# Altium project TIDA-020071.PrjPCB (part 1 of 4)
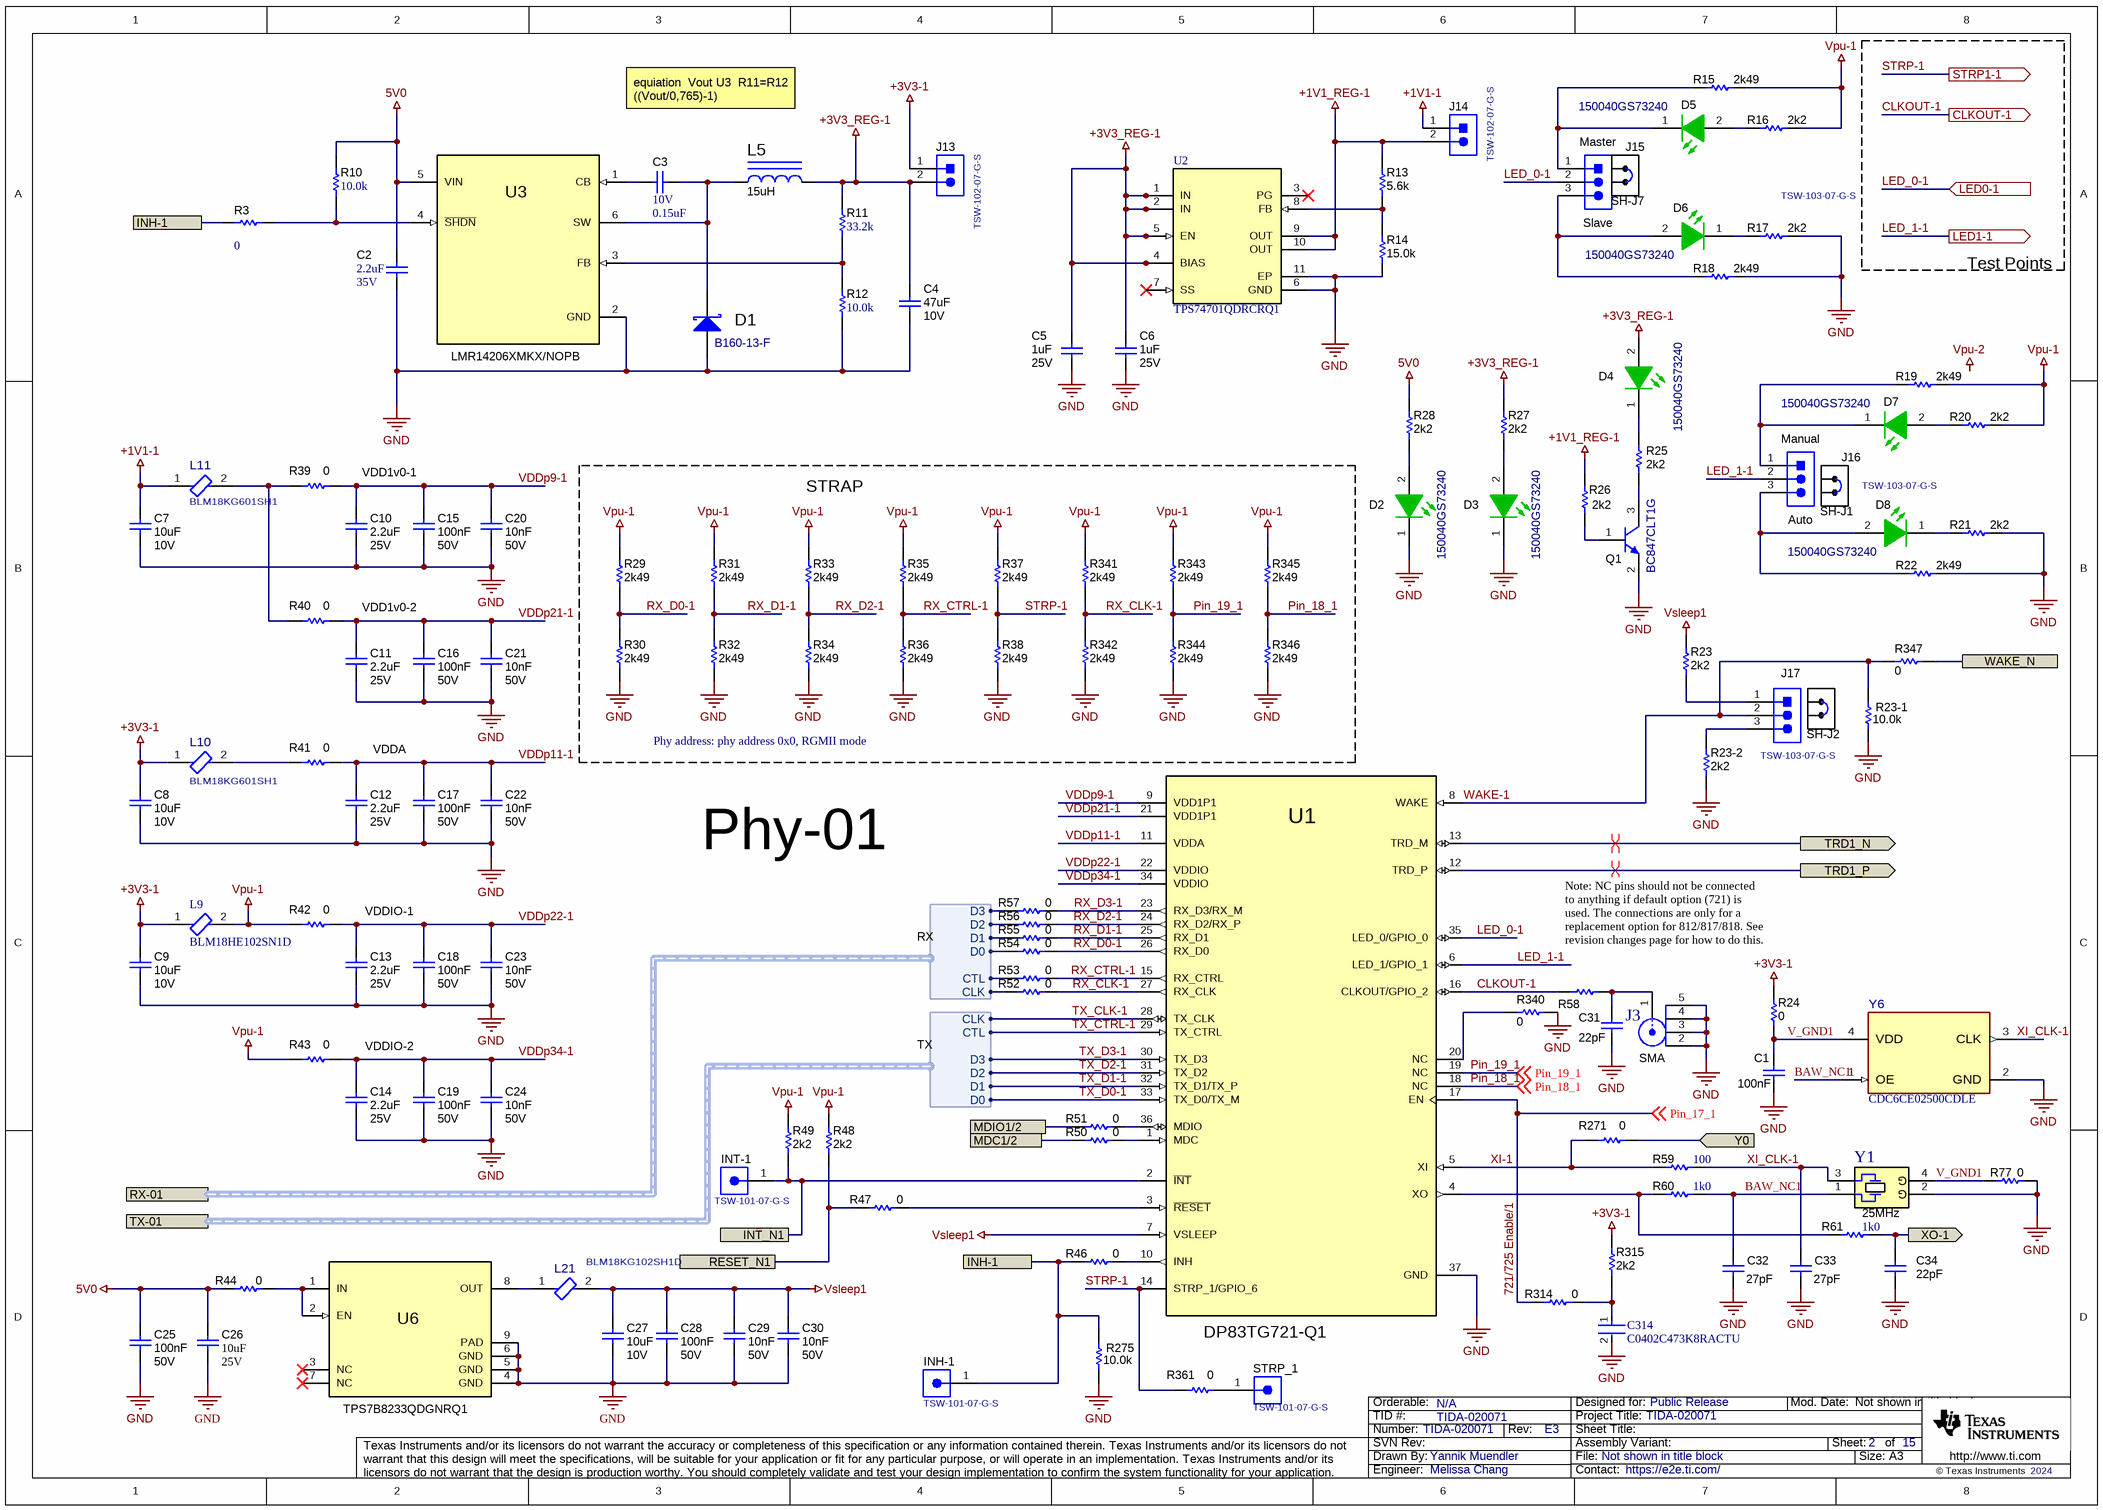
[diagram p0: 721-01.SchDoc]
CopyrightYear: 2024; DrawnBy: Yannik Muendler; EVM_orderable: N/A; PCB_Layout: TESSOLVE; PCB_Rev: E3; PRJ_Customer: Public Release; PRJ_Engineer: Melissa Chang; PRJ_Number: TIDA-020071; PRJ_Title: TIDA-020071; SCH_Rev: E3; TechSupport: https://e2e.ti.com/; TID: TIDA-020071
15 sheets, 793 parts. Net scope: flat (ports and power ports of the same name join across sheets).
Board file: TIDA-020071.PcbDoc
Sheets:
  721-01.SchDoc
  721-02.SchDoc
  818-03.SchDoc
  818-04.SchDoc
  CLOCK.SchDoc
  AVB Headers.SchDoc
  Connector.SchDoc
  Conn-Rb-01.SchDoc
  Conn-Rb-02.SchDoc
  Conn-TE-01.SchDoc
  Conn-TE-02.SchDoc
  Hardware.SchDoc
  MDIO_MUX.SchDoc
  HSS and Memory.SchDoc
  Reset.SchDoc

## Sheet 721-01.SchDoc
size A3; Date: Not shown in title block; ApprovedBy: Not shown in title block; CheckedBy: Not shown in title block; Author: Not shown in title block; CompanyName: Not shown in title block; Engineer: Not shown in title block; Organization: Not shown in title block; Address1: Not shown in title block; Address2: Not shown in title block; Address3: Not shown in title block; Address4: Not shown in title block; DocumentNumber: 2; Revision: Use project parameter SCH_Rev; SheetNumber: 2; SheetTotal: 15; PageSetup: Record=PageOptions¦CenterHorizontal=True¦CenterVertical=True¦PrintScale=1.00¦XCorrection=1.00¦YCorrection=1.00¦PrintKind=0¦BorderSize=5000000¦LeftOffset=0¦BottomOffset=0¦Orientation=2¦PaperLength=1000¦PaperWidth=1000¦Scale=100¦PaperSource=15¦PrintQuality=600¦MediaType=1¦DitherType=10¦PaperKind=Letter¦PrintScaleMode=1

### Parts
C1  ValueDisplayed: 100nF  [0402]  (hidden comment: C1005X5R1H104K050BB)
C2  VDC_V: 35V  ValueDisplayed: 2.2uF  [0603]  (hidden comment: C1608X5R1V225K080AC)
C3  VDC_V: 10V  ValueDisplayed: 0.15uF  [0402]  (hidden comment: GRM155R61A154KE19D)
C4  VDC_V: 10V  ValueDisplayed: 47uF  [0805_HV]  (hidden comment: C2012X5R1A476M125AC)
C5  VDC_V: 25V  ValueDisplayed: 1uF  [0402]  (hidden comment: GRM155R61E105KA12D)
C6  VDC_V: 25V  ValueDisplayed: 1uF  [0402]  (hidden comment: GRM155R61E105KA12D)
C7  VDC_V: 10V  ValueDisplayed: 10uF  [0402]  (hidden comment: GRM155R61A106ME11)
C8  VDC_V: 10V  ValueDisplayed: 10uF  [0402]  (hidden comment: GRM155R61A106ME11)
C9  VDC_V: 10V  ValueDisplayed: 10uF  [0402]  (hidden comment: GRM155R61A106ME11)
C10  VDC_V: 25V  ValueDisplayed: 2.2uF  [0402]  (hidden comment: C1005X5R1E225K050BC)
C11  VDC_V: 25V  ValueDisplayed: 2.2uF  [0402]  (hidden comment: C1005X5R1E225K050BC)
C12  VDC_V: 25V  ValueDisplayed: 2.2uF  [0402]  (hidden comment: C1005X5R1E225K050BC)
C13  VDC_V: 25V  ValueDisplayed: 2.2uF  [0402]  (hidden comment: C1005X5R1E225K050BC)
C14  VDC_V: 25V  ValueDisplayed: 2.2uF  [0402]  (hidden comment: C1005X5R1E225K050BC)
C15  VDC_V: 50V  ValueDisplayed: 100nF  [0402]  (hidden comment: C1005X5R1H104K050BB)
C16  VDC_V: 50V  ValueDisplayed: 100nF  [0402]  (hidden comment: C1005X5R1H104K050BB)
C17  VDC_V: 50V  ValueDisplayed: 100nF  [0402]  (hidden comment: C1005X5R1H104K050BB)
C18  VDC_V: 50V  ValueDisplayed: 100nF  [0402]  (hidden comment: C1005X5R1H104K050BB)
C19  VDC_V: 50V  ValueDisplayed: 100nF  [0402]  (hidden comment: C1005X5R1H104K050BB)
C20  VDC_V: 50V  ValueDisplayed: 10nF  [0402]  (hidden comment: C0402C103J5RACTU)
C21  VDC_V: 50V  ValueDisplayed: 10nF  [0402]  (hidden comment: C0402C103J5RACTU)
C22  VDC_V: 50V  ValueDisplayed: 10nF  [0402]  (hidden comment: C0402C103J5RACTU)
C23  VDC_V: 50V  ValueDisplayed: 10nF  [0402]  (hidden comment: C0402C103J5RACTU)
C24  VDC_V: 50V  ValueDisplayed: 10nF  [0402]  (hidden comment: C0402C103J5RACTU)
C25  VDC_V: 50V  ValueDisplayed: 100nF  [0402]  (hidden comment: C1005X5R1H104K050BB)
C26  VDC_V: 25V  ValueDisplayed: 10uF  [0603]  (hidden comment: C1608X5R1E106M080AC)
C27  VDC_V: 10V  ValueDisplayed: 10uF  [0402]  (hidden comment: GRM155R61A106ME11)
C28  VDC_V: 50V  ValueDisplayed: 100nF  [0402]  (hidden comment: C1005X5R1H104K050BB)
C29  VDC_V: 50V  ValueDisplayed: 10nF  [0402]  (hidden comment: C0402C103J5RACTU)
C30  VDC_V: 50V  ValueDisplayed: 10nF  [0402]  (hidden comment: C0402C103J5RACTU)
C31  ValueDisplayed: 22pF  [0402]  (hidden comment: GRM1555C1H220FA01D)
C32  ValueDisplayed: 27pF  [0402]  (hidden comment: C0402C270J5GACTU)
C33  ValueDisplayed: 27pF  [0402]  (hidden comment: C0402C270J5GACTU)
C34  ValueDisplayed: 22pF  [0402]  (hidden comment: GRM1555C1H220FA01D)
C314  C0402C473K8RACTU  [FP-C0402-BB-MFG]
D1  B160-13-F  [SMA]
D2  150040GS73240  [WL-SMCC_0402_Green]
D3  150040GS73240  [WL-SMCC_0402_Green]
D4  150040GS73240  [WL-SMCC_0402_Green]
D5  150040GS73240  [WL-SMCC_0402_Green]
D6  150040GS73240  [WL-SMCC_0402_Green]
D7  150040GS73240  [WL-SMCC_0402_Green]
D8  150040GS73240  [WL-SMCC_0402_Green]
INH-1  TSW-101-07-G-S  [TSW-101-07-G-S]
INT-1  TSW-101-07-G-S  [TSW-101-07-G-S]
J3  CompType: SMA  [AMPHENOL_901-144-8RFX]  (hidden comment: 901-144-8RFX)
J13  TSW-102-07-G-S  [TSW-102-07-G-S]
J14  TSW-102-07-G-S  [TSW-102-07-G-S]
J15  TSW-103-07-G-S  [TSW-103-07-G-S]
J16  TSW-103-07-G-S  [TSW-103-07-G-S]
J17  TSW-103-07-G-S  [TSW-103-07-G-S]
L5  ValueDisplayed: 15uH  [WE-TPC-LH]  (hidden comment: 744053150)
L9  BLM18HE102SN1D  [FP-BLM18-0_15-t0_8-MFG]
L10  BLM18KG601SH1  [FP-BLM18KG601SH1_0603 (1608 Metric)-MFG]
L11  BLM18KG601SH1  [FP-BLM18KG601SH1_0603 (1608 Metric)-MFG]
L21  BLM18KG102SH1D  [FP-BLM18KG102SH1D_0603-MFG]
Q1  BC847CLT1G  [SOT-23]
R3  ValueDisplayed: 0  [0402]  (hidden comment: CRCW04020000Z0ED)
R10  ValueDisplayed: 10.0k  [0402]  (hidden comment: CRCW040210K0FKED)
R11  ValueDisplayed: 33.2k  [0402]  (hidden comment: CRCW040233K2FKED)
R12  ValueDisplayed: 10.0k  [0402]  (hidden comment: CRCW040210K0FKED)
R13  ValueDisplayed: 5.6k  [0402]  (hidden comment: CRCW04025K60JNED)
R14  ValueDisplayed: 15.0k  [0402]  (hidden comment: CRCW040215K0FKED)
R15  ValueDisplayed: 2k49  [0402]  (hidden comment: CRCW04022K49FKED)
R16  ValueDisplayed: 2k2  [0402]  (hidden comment: CRCW04022K20JNED)
R17  ValueDisplayed: 2k2  [0402]  (hidden comment: CRCW04022K20JNED)
R18  ValueDisplayed: 2k49  [0402]  (hidden comment: CRCW04022K49FKED)
R19  ValueDisplayed: 2k49  [0402]  (hidden comment: CRCW04022K49FKED)
R20  ValueDisplayed: 2k2  [0402]  (hidden comment: CRCW04022K20JNED)
R21  ValueDisplayed: 2k2  [0402]  (hidden comment: CRCW04022K20JNED)
R22  ValueDisplayed: 2k49  [0402]  (hidden comment: CRCW04022K49FKED)
R23  ValueDisplayed: 2k2  [0402]  (hidden comment: CRCW04022K20JNED)
R23-1  ValueDisplayed: 10.0k  [0402]  (hidden comment: CRCW040210K0FKED)
R23-2  ValueDisplayed: 2k2  [0402]  (hidden comment: CRCW04022K20JNED)
R24  ValueDisplayed: 0  [0402]  (hidden comment: ERJ-2GE0R00X)
R25  ValueDisplayed: 2k2  [0402]  (hidden comment: CRCW04022K20JNED)
R26  ValueDisplayed: 2k2  [0402]  (hidden comment: CRCW04022K20JNED)
R27  ValueDisplayed: 2k2  [0402]  (hidden comment: CRCW04022K20JNED)
R28  ValueDisplayed: 2k2  [0402]  (hidden comment: CRCW04022K20JNED)
R29  ValueDisplayed: 2k49  [0402]  (hidden comment: CRCW04022K49FKED)
R30  ValueDisplayed: 2k49  [0402]  (hidden comment: CRCW04022K49FKED)
R31  ValueDisplayed: 2k49  [0402]  (hidden comment: CRCW04022K49FKED)
R32  ValueDisplayed: 2k49  [0402]  (hidden comment: CRCW04022K49FKED)
R33  ValueDisplayed: 2k49  [0402]  (hidden comment: CRCW04022K49FKED)
R34  ValueDisplayed: 2k49  [0402]  (hidden comment: CRCW04022K49FKED)
R35  ValueDisplayed: 2k49  [0402]  (hidden comment: CRCW04022K49FKED)
R36  ValueDisplayed: 2k49  [0402]  (hidden comment: CRCW04022K49FKED)
R37  ValueDisplayed: 2k49  [0402]  (hidden comment: CRCW04022K49FKED)
R38  ValueDisplayed: 2k49  [0402]  (hidden comment: CRCW04022K49FKED)
R39  ValueDisplayed: 0  [0402]  (hidden comment: CRCW04020000Z0EDHP)
R40  ValueDisplayed: 0  [0402]  (hidden comment: CRCW04020000Z0EDHP)
R41  ValueDisplayed: 0  [0402]  (hidden comment: CRCW04020000Z0EDHP)
R42  ValueDisplayed: 0  [0402]  (hidden comment: CRCW04020000Z0EDHP)
R43  ValueDisplayed: 0  [0402]  (hidden comment: CRCW04020000Z0EDHP)
R44  ValueDisplayed: 0  [0402]  (hidden comment: CRCW04020000Z0EDHP)
R46  ValueDisplayed: 0  [0402]  (hidden comment: CRCW04020000Z0EDHP)
R47  ValueDisplayed: 0  [0402]  (hidden comment: CRCW04020000Z0EDHP)
R48  ValueDisplayed: 2k2  [0402]  (hidden comment: CRCW04022K20JNED)
R49  ValueDisplayed: 2k2  [0402]  (hidden comment: CRCW04022K20JNED)
R50  ValueDisplayed: 0  [0402]  (hidden comment: CRCW04020000Z0EDHP)
R51  ValueDisplayed: 0  [0402]  (hidden comment: CRCW04020000Z0EDHP)
R52  ValueDisplayed: 0  [0402]  (hidden comment: CRCW04020000Z0EDHP)
R53  ValueDisplayed: 0  [0402]  (hidden comment: CRCW04020000Z0EDHP)
R54  ValueDisplayed: 0  [0402]  (hidden comment: CRCW04020000Z0EDHP)
R55  ValueDisplayed: 0  [0402]  (hidden comment: CRCW04020000Z0EDHP)
R56  ValueDisplayed: 0  [0402]  (hidden comment: CRCW04020000Z0EDHP)
R57  ValueDisplayed: 0  [0402]  (hidden comment: CRCW04020000Z0EDHP)
R58  ERJ-2GE0R00X  [0402]  (value not drawn)
R59  ValueDisplayed: 100  [0402]  (hidden comment: CRCW0402100RFKED)
R60  ValueDisplayed: 1k0  [0402]  (hidden comment: CRCW04021K00FKED)
R61  ValueDisplayed: 1k0  [0402]  (hidden comment: CRCW04021K00FKED)
R77  ValueDisplayed: 0  [0402]  (hidden comment: ERJ-2GE0R00X)
R271  ValueDisplayed: 0  [0402]  (hidden comment: ERJ-2GE0R00X)
R275  ValueDisplayed: 10.0k  [0402]  (hidden comment: CRCW040210K0FKED)
R314  ValueDisplayed: 0  [0402]  (hidden comment: CRCW04020000Z0EDHP)
R315  ValueDisplayed: 2k2  [0402]  (hidden comment: CRCW04022K20JNED)
R340  ValueDisplayed: 0  [0402]  (hidden comment: ERJ-2GE0R00X)
R341  ValueDisplayed: 2k49  [0402]  (hidden comment: CRCW04022K49FKED)
R342  ValueDisplayed: 2k49  [0402]  (hidden comment: CRCW04022K49FKED)
R343  ValueDisplayed: 2k49  [0402]  (hidden comment: CRCW04022K49FKED)
R344  ValueDisplayed: 2k49  [0402]  (hidden comment: CRCW04022K49FKED)
R345  ValueDisplayed: 2k49  [0402]  (hidden comment: CRCW04022K49FKED)
R346  ValueDisplayed: 2k49  [0402]  (hidden comment: CRCW04022K49FKED)
R347  ValueDisplayed: 0  [0402]  (hidden comment: ERJ-2GE0R00X)
R361  ValueDisplayed: 0  [0402]  (hidden comment: ERJ-2GE0R00X)
SH-J1  881545-2  [TE_881545-2]  (value not drawn)  (mechanical)
SH-J2  881545-2  [TE_881545-2]  (value not drawn)  (mechanical)
SH-J7  881545-2  [TE_881545-2]  (value not drawn)  (mechanical)
STRP_1  TSW-101-07-G-S  [TSW-101-07-G-S]
U1  PartNumber: DP83TG721-Q1  [RND0036A]  (hidden comment: DP83TG720SWRNDRQ1)
U2  TPS74701QDRCRQ1  [DRC0010A]
U3  LMR14206XMKX/NOPB  [DDC0006A_N]
U6  TPS7B8233QDGNRQ1  [DGN0008D_N]
Y1  Frequency_Fixed: 25MHz  [Abracon_ABM8AIG]  (hidden comment: ABM8AIG-25.000MHZ-12-2Z-T3)
Y6  CDC6CE02500CDLE  [DLE0004A-MFG]

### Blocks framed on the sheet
STRAP: R29-R38 R341-R346

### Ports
CLKOUT-1 (out), INH-1, INT_N1, LED0-1 (in), LED1-1 (out), MDC1/2, MDIO1/2, RESET_N1, RX-01 (harness RX), STRP1-1 (out), TRD1_N (out), TRD1_P (out), TX-01 (harness TX), WAKE_N, XO-1 (out), Y0 (in)

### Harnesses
TX: D0, D1, D2, D3, CTL, CLK
RX: D0, D1, D2, D3, CTL, CLK

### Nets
5V0: C2.1 C25.1 C26.1 R10.2 R28.2 R44.2 U3.5(VIN)
+1V1-1: C7.1 J14.1 L11.1
+1V1_REG-1: J14.2 R13.2 R26.2 U2.9(OUT) U2.10(OUT)
+3V3-1: C8.1 C9.1 J13.1 L9.1 L10.1 R24.1 R315.1
+3V3_REG-1: C4.1 C5.1 C6.1 D4.2(A) J13.2 L5.2 R11.2 R27.2 U2.1(IN) U2.2(IN) U2.4(BIAS) U2.5(EN)
GND: C1.2 C2.2 C4.2 C5.2 C6.2 C7.2 C8.2 C9.2 C10.2 C11.2 C12.2 C13.2 C14.2 C15.2 C16.2 C17.2 C18.2 C19.2 C20.2 C21.2 C22.2 C23.2 C24.2 C25.2 C26.2 C27.2 C28.2 C29.2 C30.2 C31.2 C32.2 C33.2 C34.2 C314.2 D1.2(A) D2.1(K) D3.1(K) J3.2 J3.3 J3.4 J3.5 Q1.2(E) R12.1 R14.1 R17.2 R18.2 R21.2 R22.2 R23-1.1 R23-2.2 R30.1 R32.1 R34.1 R36.1 R38.1 R77.2 R275.1 R340.2 R342.1 R344.1 R346.1 U1.37(GND) U2.6(GND) U2.11(EP) U3.2(GND) U6.4(GND) U6.5(GND) U6.6(GND) U6.9(PAD) Y1.2(GND) Y6.2(GND)
Vpu-1: L9.2 R15.2 R16.2 R19.2 R20.2 R29.2 R31.2 R33.2 R35.2 R37.2 R42.2 R43.2 R48.2 R49.2 R341.2 R343.2 R345.2
Vsleep1: C27.1 C28.1 C29.1 C30.1 L21.2 R23.1 U1.7(VSLEEP)
721/725 Enable/1: R314.2 U1.17(EN) ; off-sheet Pin_17_1  [also labelled Pin_17_1]
BAW_NC1: C32.1 R60.1 Y1.1 Y6.1(OE)
CLKOUT-1: R58.1 U1.16(CLKOUT/GPIO_2) ; port CLKOUT-1
INH-1: INH-1.1 R3.1 R46.2 R275.2 ; port INH-1
INT_N1: INT-1.1 R49.1 U1.2(~{INT}) ; port INT_N1
LED_0-1: J15.2 U1.35(LED_0/GPIO_0) ; port LED0-1
LED_1-1: J16.2 U1.6(LED_1/GPIO_1) ; port LED1-1
MDC1/2: R50.2 ; port MDC1/2
MDIO1/2: R51.2 ; port MDIO1/2
P1-R1-RCLK: R52.2 ; port RX-01.CLK
P1-R1-RCTL: R53.2 ; port RX-01.CTL
P1-R1-RD0: R54.2 ; port RX-01.D0
P1-R1-RD1: R55.2 ; port RX-01.D1
P1-R1-RD2: R56.2 ; port RX-01.D2
P1-R1-RD3: R57.2 ; port RX-01.D3
Pin_18_1: R345.1 R346.2 U1.18(NC) ; off-sheet Pin_18_1
Pin_19_1: R343.1 R344.2 U1.19(NC) ; off-sheet Pin_19_1
RESET_N1: R47.2 R48.1 ; port RESET_N1
RX_CLK-1: R52.1 R341.1 R342.2 U1.27(RX_CLK)
RX_CTRL-1: R35.1 R36.2 R53.1 U1.15(RX_CTRL)
RX_D0-1: R29.1 R30.2 R54.1 U1.26(RX_D0)
RX_D1-1: R31.1 R32.2 R55.1 U1.25(RX_D1)
RX_D2-1: R33.1 R34.2 R56.1 U1.24(RX_D2/RX_P)
RX_D3-1: R57.1 U1.23(RX_D3/RX_M)
STRP-1: R37.1 R38.2 R361.1 U1.14(STRP_1/GPIO_6) ; port STRP1-1
TRD1_N: U1.13(TRD_M) ; port TRD1_N
TRD1_P: U1.12(TRD_P) ; port TRD1_P
TX_CLK-1: U1.28(TX_CLK) ; port TX-01.CLK
TX_CTRL-1: U1.29(TX_CTRL) ; port TX-01.CTL
TX_D0-1: U1.33(TX_D0/TX_M) ; port TX-01.D0
TX_D1-1: U1.32(TX_D1/TX_P) ; port TX-01.D1
TX_D2-1: U1.31(TX_D2) ; port TX-01.D2
TX_D3-1: U1.30(TX_D3) ; port TX-01.D3
V_GND1: C1.1 R24.2 R77.1 Y1.4(GND) Y6.4(VDD)
VDDp9-1: C10.1 C15.1 C20.1 R39.1 U1.9(VDD1P1)
VDDp11-1: C12.1 C17.1 C22.1 R41.1 U1.11(VDDA)
VDDp21-1: C11.1 C16.1 C21.1 R40.1 U1.21(VDD1P1)
VDDp22-1: C13.1 C18.1 C23.1 R42.1 U1.22(VDDIO)
VDDp34-1: C14.1 C19.1 C24.1 R43.1 U1.34(VDDIO)
WAKE-1: J17.2 R23-1.2 R347.1 U1.8(WAKE)
WAKE_N: R347.2 ; port WAKE_N
XI-1: R59.2 R271.1 U1.5(XI)
XI_CLK-1: C33.1 R59.1 Y1.3 Y6.3(CLK)
XO-1: C34.1 R61.1 ; port XO-1
Y0: R271.2 ; port Y0
NetC3_1: C3.1 D1.1(K) L5.1 U3.6(SW)
NetC3_2: C3.2 U3.1(CB)
NetC31_1: C31.1 J3.1 R58.2
NetC314_1: C314.1 R314.1 R315.2
NetD2_2: D2.2(A) R28.1
NetD3_2: D3.2(A) R27.1
NetD4_1: D4.1(K) R25.2
NetD5_1: D5.1(K) J15.1 R15.1
NetD5_2: D5.2(A) R16.1
NetD6_1: D6.1(K) R17.1
NetD6_2: D6.2(A) J15.3 R18.1
NetD7_1: D7.1(K) J16.1 R19.1
NetD7_2: D7.2(A) R20.1
NetD8_1: D8.1(K) R21.1
NetD8_2: D8.2(A) J16.3 R22.1
NetJ17_1: J17.1 R23.2
NetJ17_3: J17.3 R23-2.1
NetL10_2: L10.2 R41.2
NetL11_2: L11.2 R39.2 R40.2
NetL21_1: L21.1 U6.8(OUT)
NetQ1_1: Q1.1(B) R26.1
NetQ1_3: Q1.3(C) R25.1
NetR3_2: R3.2 R10.1 U3.4(~{SHDN})
NetR11_1: R11.1 R12.2 U3.3(FB)
NetR13_1: R13.1 R14.2 U2.8(FB)
NetR44_1: R44.1 U6.1(IN) U6.2(EN)
NetR46_1: R46.1 U1.10(INH)
NetR47_1: R47.1 U1.3(~{RESET})
NetR50_1: R50.1 U1.1(MDC)
NetR51_1: R51.1 U1.36(MDIO)
NetR60_2: R60.2 R61.2 U1.4(XO)
NetR340_1: R340.1 U1.20(NC)
NetR361_2: R361.2 STRP_1.1

Not connected (* = marked no-connect by the designer): U2 3(PG)* 7(SS)*; U6 3(NC)* 7(NC)*

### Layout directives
differential pair: TRD1_N, TRD1_P

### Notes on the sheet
- equiation  Vout U3  R11=R12 ((Vout/0,765)-1)
- (near J15) Master
- (near J15) Slave
- Test Points
- (near J16) Manual
- VDD1v0-1
- Auto
- VDD1v0-2
- VDDA
- Phy address: phy address 0x0, RGMII mode
- Phy-01
- VDDIO-1
- Note: NC pins should not be connected to anything if default option (721) is used. The connections are only for a replacement option for 812/817/818. See revision changes page for how to do this.
- VDDIO-2
- Labels drawn without touching a wire or pin: Vpu-2

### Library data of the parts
C1 = CMP-0006279-2: CAP, CERM, 0.1 uF, 50 V, +/- 10%, X5R, 0402; Manufacturer: TDK; TaMin_C: -55°C; ESR_ohm: 0.039064; Polarized: N; SizeAreaWB_mm2: 3; Value1: 0.039064 ohm; U/M: EA; Value: 0.1uF; TaMax_C: 85°C; SizeZ_mm: 0.6; SizeX_mm: 1; SizeY_mm: 0.5; Value2: 50V; IRMS_A: 814.669mA; AEC Category: Q200
C2 = CMP-0007020-5: CAP, CERM, 2.2 uF, 35 V, +/- 10%, X5R, 0603; Manufacturer: TDK; TaMin_C: -55°C; ESR_ohm: 7.674m; Polarized: N; SizeAreaWB_mm2: 4.68; Value1: 0.007674 ohm; U/M: EA; Value: 2.2uF; TaMax_C: 85°C; SizeZ_mm: 1; SizeX_mm: 1.6; SizeY_mm: 0.8; SizeArea_mm2: 1.28; Cap_F: 2.2µF; IRMS_A: 1.87823A; AEC Category: Q200
C3 = CMP-0006567-2: CAP, CERM, 0.15 uF, 10 V, +/- 10%, X5R, 0402; Manufacturer: MuRata; TaMin_C: -55°C; Polarized: N; SizeAreaWB_mm2: 3; Value1: Unknown; U/M: EA; Value: 0.15uF; TaMax_C: 85°C; SizeZ_mm: 0.6; SizeX_mm: 1; SizeY_mm: 0.5; Cap_F: 150nF; AEC Category: Q200
C4 = CMP-0007825-2: CAP, CERM, 47 uF, 10 V, +/- 20%, X5R, 0805; Manufacturer: TDK; TaMin_C: -55°C; ESR_ohm: 2.94m; Polarized: N; SizeAreaWB_mm2: 6.75; Value1: 0.00294 ohm; U/M: EA; Value: 47uF; TaMax_C: 85°C; SizeZ_mm: 1.45; SizeX_mm: 2; SizeY_mm: 1.25; Cap_Case: 0805; SizeArea_mm2: 2.5; Cap_F: 47µF; IRMS_A: 3.80451A; AEC Category: Q200
C5 C6 = CMP-0006608-2: CAP, CERM, 1 uF, 25 V, +/- 10%, X5R, 0402; Manufacturer: MuRata; TaMin_C: -55°C; Polarized: N; SizeAreaWB_mm2: 3; Value1: Unknown; U/M: EA; Value: 1uF; TaMax_C: 85°C; SizeZ_mm: 0.6; SizeX_mm: 1; SizeY_mm: 0.5; Cap_F: 1µF; AEC Category: Q200
C7-C9 C27 = CMP-0006564-2: CAP, CERM, 10 uF, 10 V, +/- 20%, X5R, 0402; Manufacturer: MuRata; TaMin_C: -55°C; Polarized: N; SizeAreaWB_mm2: 3; Value1: Unknown; U/M: EA; Value: 10uF; TaMax_C: 85°C; SizeZ_mm: 0.6; SizeX_mm: 1; SizeY_mm: 0.5; Cap_F: 10µF; AEC Category: Q200
C10-C14 = CMP-0006278-2: CAP, CERM, 2.2 uF, 25 V, +/- 10%, X5R, 0402; Manufacturer: TDK; TaMin_C: -55°C; Polarized: N; SizeAreaWB_mm2: 3; Value1: Unknown; U/M: EA; Value: 2.2uF; TaMax_C: 85°C; SizeZ_mm: 0.6; SizeX_mm: 1; SizeY_mm: 0.5; Cap_F: 2.2µF; AEC Category: Q200
C15-C19 C25 C28 = CMP-0006279-2: CAP, CERM, 0.1 uF, 50 V, +/- 10%, X5R, 0402; Manufacturer: TDK; TaMin_C: -55°C; ESR_ohm: 39.064m; Polarized: N; SizeAreaWB_mm2: 3; Value1: 0.039064 ohm; U/M: EA; Value: 0.1uF; TaMax_C: 85°C; SizeZ_mm: 0.6; SizeX_mm: 1; SizeY_mm: 0.5; IRMS_A: 814.669mA; AEC Category: Q200
C20-C24 C29 C30 = CMP-0006236-2: CAP, CERM, 0.01 uF, 50 V, +/- 5%, X7R, 0402; Manufacturer: Kemet; TaMin_C: -55°C; Polarized: N; SizeAreaWB_mm2: 3; Value1: Unknown; U/M: EA; Value: 0.01uF; TaMax_C: 125°C; SizeZ_mm: 0.6; SizeX_mm: 1; SizeY_mm: 0.5; AEC Category: Q200
C26 = CMP-0007007-5: CAP, CERM, 10 uF, 25 V, +/- 20%, X5R, 0603; Manufacturer: TDK; TaMin_C: -55°C; ESR_ohm: 4.639m; Polarized: N; SizeAreaWB_mm2: 4.68; Value1: 0.004639 ohm; U/M: EA; Value: 10uF; TaMax_C: 85°C; SizeZ_mm: 1; SizeX_mm: 1.6; SizeY_mm: 0.8; SizeArea_mm2: 1.28; Cap_F: 10µF; IRMS_A: 2.41407A; AEC Category: Q200
C31 C34 = CMP-0006438-2: CAP, CERM, 22 pF, 50 V, +/- 1%, C0G/NP0, 0402; Manufacturer: MuRata; TaMin_C: -55°C; Polarized: N; SizeAreaWB_mm2: 3; Value1: Unknown; U/M: EA; Value: 22pF; TaMax_C: 125°C; SizeZ_mm: 0.6; SizeX_mm: 1; SizeY_mm: 0.5; Value2: 50V; AEC Category: Q200
C32 C33 = CMP-0750098-1: CAP, CERM, 27 pF, 50 V,+/- 5%, C0G/NP0, 0402; Manufacturer: Kemet; SizeX_mm: 1; TaMin_C: -55°C; Value: 27pF; Polarized: N; SizeAreaWB_mm2: 3; SizeArea_mm2: 0.5; Green_REACh: Passed; Green_Lifecycle: Active; Value2: 50V; U/M: EA; AEC Category: Q200; SizeZ_mm: 0.6; TaMax_C: 125°C
C314 = CMP-2008-02147-2: Cap Ceramic 0.047uF 10V X7R 10% SMD 0402 125°C Paper T/R; Manufacturer: Kemet; Temperature Coefficient: 15%; Value: 47,000 pF; Tolerance: 0.1
D1 = CMP-0028389-2: Diode, Schottky, 60 V, 1 A, SMA; Manufacturer: Diodes Inc.; Green_Lifecycle: Not Set; SizeAreaWB_mm2: 37.3428; Green_REACh: Incomplete; TJmax_C: 150°C; AEC Category: Q101; SizeZ_mm: 2.87; RJC_CperW: 20; Io_A: 1A; SizeArea_mm2: 16.3228; Vf_V: 700mV; Value2: 0.7V; SizeY_mm: 2.92; Vr_V: 60V; SizeX_mm: 5.59; Value: 60V
D2-D8 = CMP-0081765-2: LED, Green, SMD; Manufacturer: Wurth Elektronik; Vr_V: 5V; Io_A: 20mA; Tjmax_C: 95°C; Ir_A: 10µA; Power_TotalModule: 99mW; Value2: 3.2V; SizeArea_mm2: 0.5; SizeX_mm: 1; Value1: 0.099W; Angle: 120; Type: InGaN; SizeAreaWB_mm2: 3
INH-1 INT-1 STRP_1 = CMP-0075403-1: Header, 100mil, 1pos, Gold, TH; Manufacturer: Samtec; Pitch_mm: 2.54; Cert_VDE: N; Gender: Male; Cert_CSA: Y; Voltage_V: 550V; Green_REACh: Passed; Current_A: 6.3A; CT: False; Green_Lifecycle: Active; Row_Count: 1; CNHeader: True
J3 = CMP-0055833-1: SMA Straight Jack, Gold, 50 Ohm, TH; Manufacturer: Amphenol RF; CNHeader: FALSE; Green_Lifecycle: Not Set; Green_REACh: Incomplete; CT: TRUE
J13 J14 = CMP-0075405-3: Header, 100mil, 2x1, Gold, TH; Manufacturer: Samtec; Pitch_mm: 2.54; Cert_VDE: N; Gender: Male; Cert_CSA: Y; Voltage_V: 550V; Green_REACh: Passed; Current_A: 6.3A; Green_Lifecycle: Active; Row_Count: 1
J15-J17 = CMP-0075407-2: Header, 100mil, 3x1, Gold, TH; Manufacturer: Samtec; Pitch_mm: 2.54; Cert_VDE: N; Gender: Male; Cert_CSA: Y; Voltage_V: 550V; Green_REACh: Passed; Current_A: 6.3A; Green_Lifecycle: Active; Row_Count: 1
L5 = CMP-0064420-2: Inductor, Shielded Drum Core, Ferrite, 15 uH, 1.15 A, 0.07 ohm, SMD; Manufacturer: Wurth Elektronik; Isat: 1.15A @ 35% inductance drop; Irms: 1.38A @ 30C rise; Green_Lifecycle: Active; SizeAreaWB_mm2: 60.84; DCR_ohm: 0.07; Green_REACh: Passed; Value: 15uH; Imax_A: 1.15A; SizeZ_mm: 2.8; SizeX_mm: 5.8; SizeArea_mm2: 33.64; Ind_H: 15µH; AEC Category: Q200
L9 = CMP-0686-00363-3: Chip Ferrite Bead, 0603, 1000Ω @ 100MHz, 0.35Ω, 25%, 600mA; DC Resistance (DCR): 350mR; Impedance: 1kR; Number of Circuits: 1; Material: Steel
L10 L11 = CMP-0089848-1: 600 Ohms @ 100MHz 1 Power Line Ferrite Bead 0603 (1608 Metric) 1.3A 150mOhm; Manufacturer: Murata; Tolerance_%: 25%; SizeZ_mm: 0.95mm; Impedance At Frequency: 600Ω @ 100MHz; AEC Qualified: Yes; AEC Grade: Grade 1; DCR_ohm: 0.15
L21 = CMP-0089381-1: 1 kOhms @ 100MHz 1 Power Line Ferrite Bead 0603 (1608 Metric) 1A 200mOhm; Manufacturer: Murata; AEC Grade: Grade 1; AEC Qualified: Yes; DCR_ohm: 0.2; Impedance At Frequency: 1kΩ @ 100MHz; SizeZ_mm: 0.95mm; Tolerance_%: 25%
Q1 = CMP-0000376-2: Transistor, NPN, 45 V, 0.1 A, SOT-23; Manufacturer: ON Semiconductor; TaMax_C: 150°C; Value2: 800; Value1: 0.1 A; Vcesat1_V: 700mV; SizeX_mm: 2.5; SizeY_mm: 3; TaMin_C: -55°C; IcRated_A: 100mA; CompType: BJT; SizeZ_mm: 1.1; Value: 45 V; SizeArea_mm2: 7.5; NPN: 1; Vceo_V: 45V; PNP: 0; AEC Category: Q101; SizeAreaWB_mm2: 14; U/M: EA
R3 = CMP-0026822-1: RES, 0, 5%, 0.063 W, 0402; Manufacturer: Vishay-Dale; Power_W: 63mW; TempCo: 200 ppm/C; Value_Code: 0000; U/M: EA; Value: 0; EIA_Code: E24; SizeX_mm: 1; SizeY_mm: 0.5; SizeZ_mm: 0.6; Value2: 0.063W; VDC_V: 50V; AEC Category: Q200
R10 R12 = CMP-0025958-3: RES, 10.0 k, 1%, 0.063 W, AEC-Q200 Grade 0, 0402; Manufacturer: Vishay-Dale; Power_W: 63mW; TempCo: 100 ppm/C; Value_Code: 10k0; Value: 10.0k; EIA_Code: E96; Res_ohm: 10k; SizeX_mm: 1; SizeY_mm: 0.5; SizeZ_mm: 0.6; Value2: 0.063W; AEC Qualified: Y; VDC_V: 50V; AEC Category: Q200; AEC Grade: 0
R11 = CMP-0026298-2: RES, 33.2 k, 1%, 0.063 W, AEC-Q200 Grade 0, 0402; Manufacturer: Vishay-Dale; Power_W: 63mW; TempCo: 100 ppm/C; Value_Code: 33k2; Value: 33.2k; EIA_Code: E96; SizeX_mm: 1; SizeY_mm: 0.5; SizeZ_mm: 0.6; Value2: 0.063W; AEC Qualified: Y; VDC_V: 50V; AEC Category: Q200; AEC Grade: 0
R13 = CMP-0026952-5: RES, 5.6 k, 5%, 0.063 W, AEC-Q200 Grade 0, 0402; Manufacturer: Vishay-Dale; Power_W: 63mW; TempCo: 200 ppm/C; Value_Code: 5k60; Value: 5.6k; EIA_Code: E24; SizeX_mm: 1; SizeY_mm: 0.5; SizeZ_mm: 0.6; Value2: 0.063W; AEC Qualified: Y; VDC_V: 50V; AEC Category: Q200; AEC Grade: 0
R14 = CMP-0026027-3: RES, 15.0 k, 1%, 0.063 W, AEC-Q200 Grade 0, 0402; Manufacturer: Vishay-Dale; Power_W: 63mW; TempCo: 100 ppm/C; Value_Code: 15k0; Value: 15.0k; EIA_Code: E96; Res_ohm: 15k; SizeX_mm: 1; SizeY_mm: 0.5; SizeZ_mm: 0.6; Value2: 0.063W; AEC Qualified: Y; VDC_V: 50V; AEC Category: Q200; AEC Grade: 0
R15 R18 R19 R22 R29-R38 R341-R346 = CMP-0026237-2: RES, 2.49 k, 1%, 0.063 W, AEC-Q200 Grade 0, 0402; Manufacturer: Vishay-Dale; Power_W: 63mW; TempCo: 100 ppm/C; Value: 2.49k; EIA_Code: E96; SizeX_mm: 1; SizeY_mm: 0.5; SizeZ_mm: 0.6; Value2: 0.063W; AEC Qualified: Y; VDC_V: 50V; AEC Category: Q200; AEC Grade: 0
R16 R17 R20 R21 R23 R23-2 R25-R28 R48 R49 R315 = CMP-0026890-5: RES, 2.2 k, 5%, 0.063 W, AEC-Q200 Grade 0, 0402; Manufacturer: Vishay-Dale; Power_W: 63mW; TempCo: 200 ppm/C; Value_Code: 2k20; Value: 2.2k; EIA_Code: E24; SizeX_mm: 1; SizeY_mm: 0.5; SizeZ_mm: 0.6; Value2: 0.063W; AEC Qualified: Y; VDC_V: 50V; AEC Category: Q200; AEC Grade: 0
R23-1 R275 = CMP-0025958-1: RES, 10.0 k, 1%, 0.063 W, 0402; Manufacturer: Vishay-Dale; Power_W: 63mW; TempCo: 100 ppm/C; Value_Code: 10k0; U/M: EA; Value: 10.0k; EIA_Code: E96; Res_ohm: 10k; SizeX_mm: 1; SizeY_mm: 0.5; SizeZ_mm: 0.6; Value2: 0.063W; VDC_V: 50V; AEC Category: Q200
R24 R58 R77 R271 R340 R347 R361 = CMP-0026992-3: RES, 0, 5%, 0.1 W, AEC-Q200 Grade 0, 0402; Manufacturer: Panasonic; Power_W: 100mW; TempCo: 600 ppm/C; Value_Code: 0000; Value: 0; EIA_Code: E24; SizeX_mm: 1; SizeY_mm: 0.5; SizeZ_mm: 0.6; Value2: 0.1W; AEC Qualified: Y; AEC Category: Q200; VDC_V: 50V; SizeAreaWB_mm2: 3
R39-R44 R46 R47 R50-R57 R314 = CMP-0081856-1: RES, 0, 0%, 0.2 W, AEC-Q200 Grade 0, 0402; Manufacturer: Vishay-Dale; SizeAreaWB_mm2: 3; SizeArea_mm2: 0.5; AEC Qualified: Y; AEC Category: Q200; Value: 0; SizeZ_mm: 0.6; Power_W: 200mW; VDC_V: 50V; Value2: 0.2W; SizeX_mm: 1
R59 = CMP-0025951-3: RES, 100, 1%, 0.063 W, AEC-Q200 Grade 0, 0402; Manufacturer: Vishay-Dale; Power_W: 63mW; TempCo: 100 ppm/C; Value_Code: 100R; Value: 100; EIA_Code: E96; SizeX_mm: 1; SizeY_mm: 0.5; SizeZ_mm: 0.6; Value2: 0.063W; AEC Qualified: Y; VDC_V: 50V; AEC Category: Q200; AEC Grade: 0
R60 R61 = CMP-0026071-3: RES, 1.00 k, 1%, 0.063 W, AEC-Q200 Grade 0, 0402; Manufacturer: Vishay-Dale; Power_W: 63mW; TempCo: 100 ppm/C; Value_Code: 1k00; Value: 1.00k; EIA_Code: E96; Res_ohm: 1k; SizeX_mm: 1; SizeY_mm: 0.5; SizeZ_mm: 0.6; Value2: 0.063W; AEC Qualified: Y; VDC_V: 50V; AEC Category: Q200; AEC Grade: 0
SH-J1 SH-J2 SH-J7 = 881545-2: Shunt, 100mil, Gold plated, Black; Manufacturer: TE Connectivity
U1 = CMP-0085268-1: Low Power Auto PHY 1000BASE-T1 Automotive Ethernet Physical Layer Transceiver, RND0036A (VQFNP-36); Alternate Manufacturer: Texas Instruments; Alternate PartNumber: DP83TG720SWRNDTQ1; SizeY_mm: 6; SizeAreaWB_mm2: 64; SizeZ_mm: 0.9; AEC Qualified: Y; SizeArea_mm2: 36; AEC Category: Q200; CompType: IC
U2 = CMP-0036364-1: Single Output Automotive LDO, 500 mA, Adjustable 0.8 to 3.6 V Output, 0.8 to 5.5 V Input, with Programmable Soft Start, 10-pin SON (DRC), -40 to 125 degC, Green (RoHS & no Sb/Br); Manufacturer: Texas Instruments; Accuracy(%): 2; Vout Adj(Min)(V): 0.8; Vdo(Typ)(mV): 50; Vout Adj(Max)(V): 3.6; SubFamily: Single Channel LDO; Vin(Max)(V): 5.5; Iq(Typ)(mA): 1; Iout(Max)(A): 0.5
U3 = CMP-0076377-2: SIMPLE SWITCHER(R) 4.5V to 42V, 0.6A Step-Down DC/DC Switching Regulator in SOT-23 Package, DDC0006A (SOT-23-T-6); Alternate PartNumber: LMR14206XMKE/NOPB; Manufacturer: Texas Instruments; SizeZ_mm: 0.87; SizeX_mm: 1.65; SizeY_mm: 2.95; SizeArea_mm2: 4.8675; CompType: IC; U/M: EA; SizeAreaWB_mm2: 10.4675
U6 = CMP-0013312-4: 300mA High-Voltage Ultra-Low-Iq Low-Dropout (LDO) Regulator, DGN0008D (VSSOP-8); Manufacturer: Texas Instruments; SizeX_mm: 5.05; SizeY_mm: 3.1; CompType: IC; SizeZ_mm: 1.1; SizeArea_mm2: 15.655; SizeAreaWB_mm2: 35.955; AEC Category: Q200; AEC Qualified: Y
Y1 = CMP-0004682-5: Crystal, 25 MHz, 12pF, AEC-Q200 Grade 1, SMD; Manufacturer: Abracon Corporation; TaMin_C: -40°C; Frequency Stability: 50 ppm; SizeAreaWB_mm2: 14.7; TaMax_C: 125°C; SizeZ_mm: 0.8; SizeX_mm: 2.5; SizeY_mm: 3.2; SizeArea_mm2: 8; AEC Category: Q200; AEC Grade: 1; AEC Qualified: Y
Y6 = CMP-0001498-1: Low Jitter, Low Power, LVCMOS Output, BAW Oscillator; Manufacturer: Texas Instruments; SizeZ_mm: 1mm; AEC Qualified: Yes; AEC Grade: Grade 1; Frequency Stability: 20ppm; Frequency_Fixed: 25MHz; Max Supply Current: 5mA; Max Supply Voltage: 3.63V; Min Supply Voltage: 1.62V; Standoff Height: 0mm

## Sheet 721-02.SchDoc
size A3; Date: Not shown in title block; ApprovedBy: Not shown in title block; CheckedBy: Not shown in title block; Author: Not shown in title block; CompanyName: Not shown in title block; Engineer: Not shown in title block; Organization: Not shown in title block; Address1: Not shown in title block; Address2: Not shown in title block; Address3: Not shown in title block; Address4: Not shown in title block; DocumentNumber: 3; Revision: Use project parameter SCH_Rev; SheetNumber: 3; SheetTotal: 15; PageSetup: Record=PageOptions¦CenterHorizontal=True¦CenterVertical=True¦PrintScale=1.00¦XCorrection=1.00¦YCorrection=1.00¦PrintKind=0¦BorderSize=5000000¦LeftOffset=0¦BottomOffset=0¦Orientation=2¦PaperLength=1000¦PaperWidth=1000¦Scale=100¦PaperSource=15¦PrintQuality=600¦MediaType=1¦DitherType=10¦PaperKind=Letter¦PrintScaleMode=1
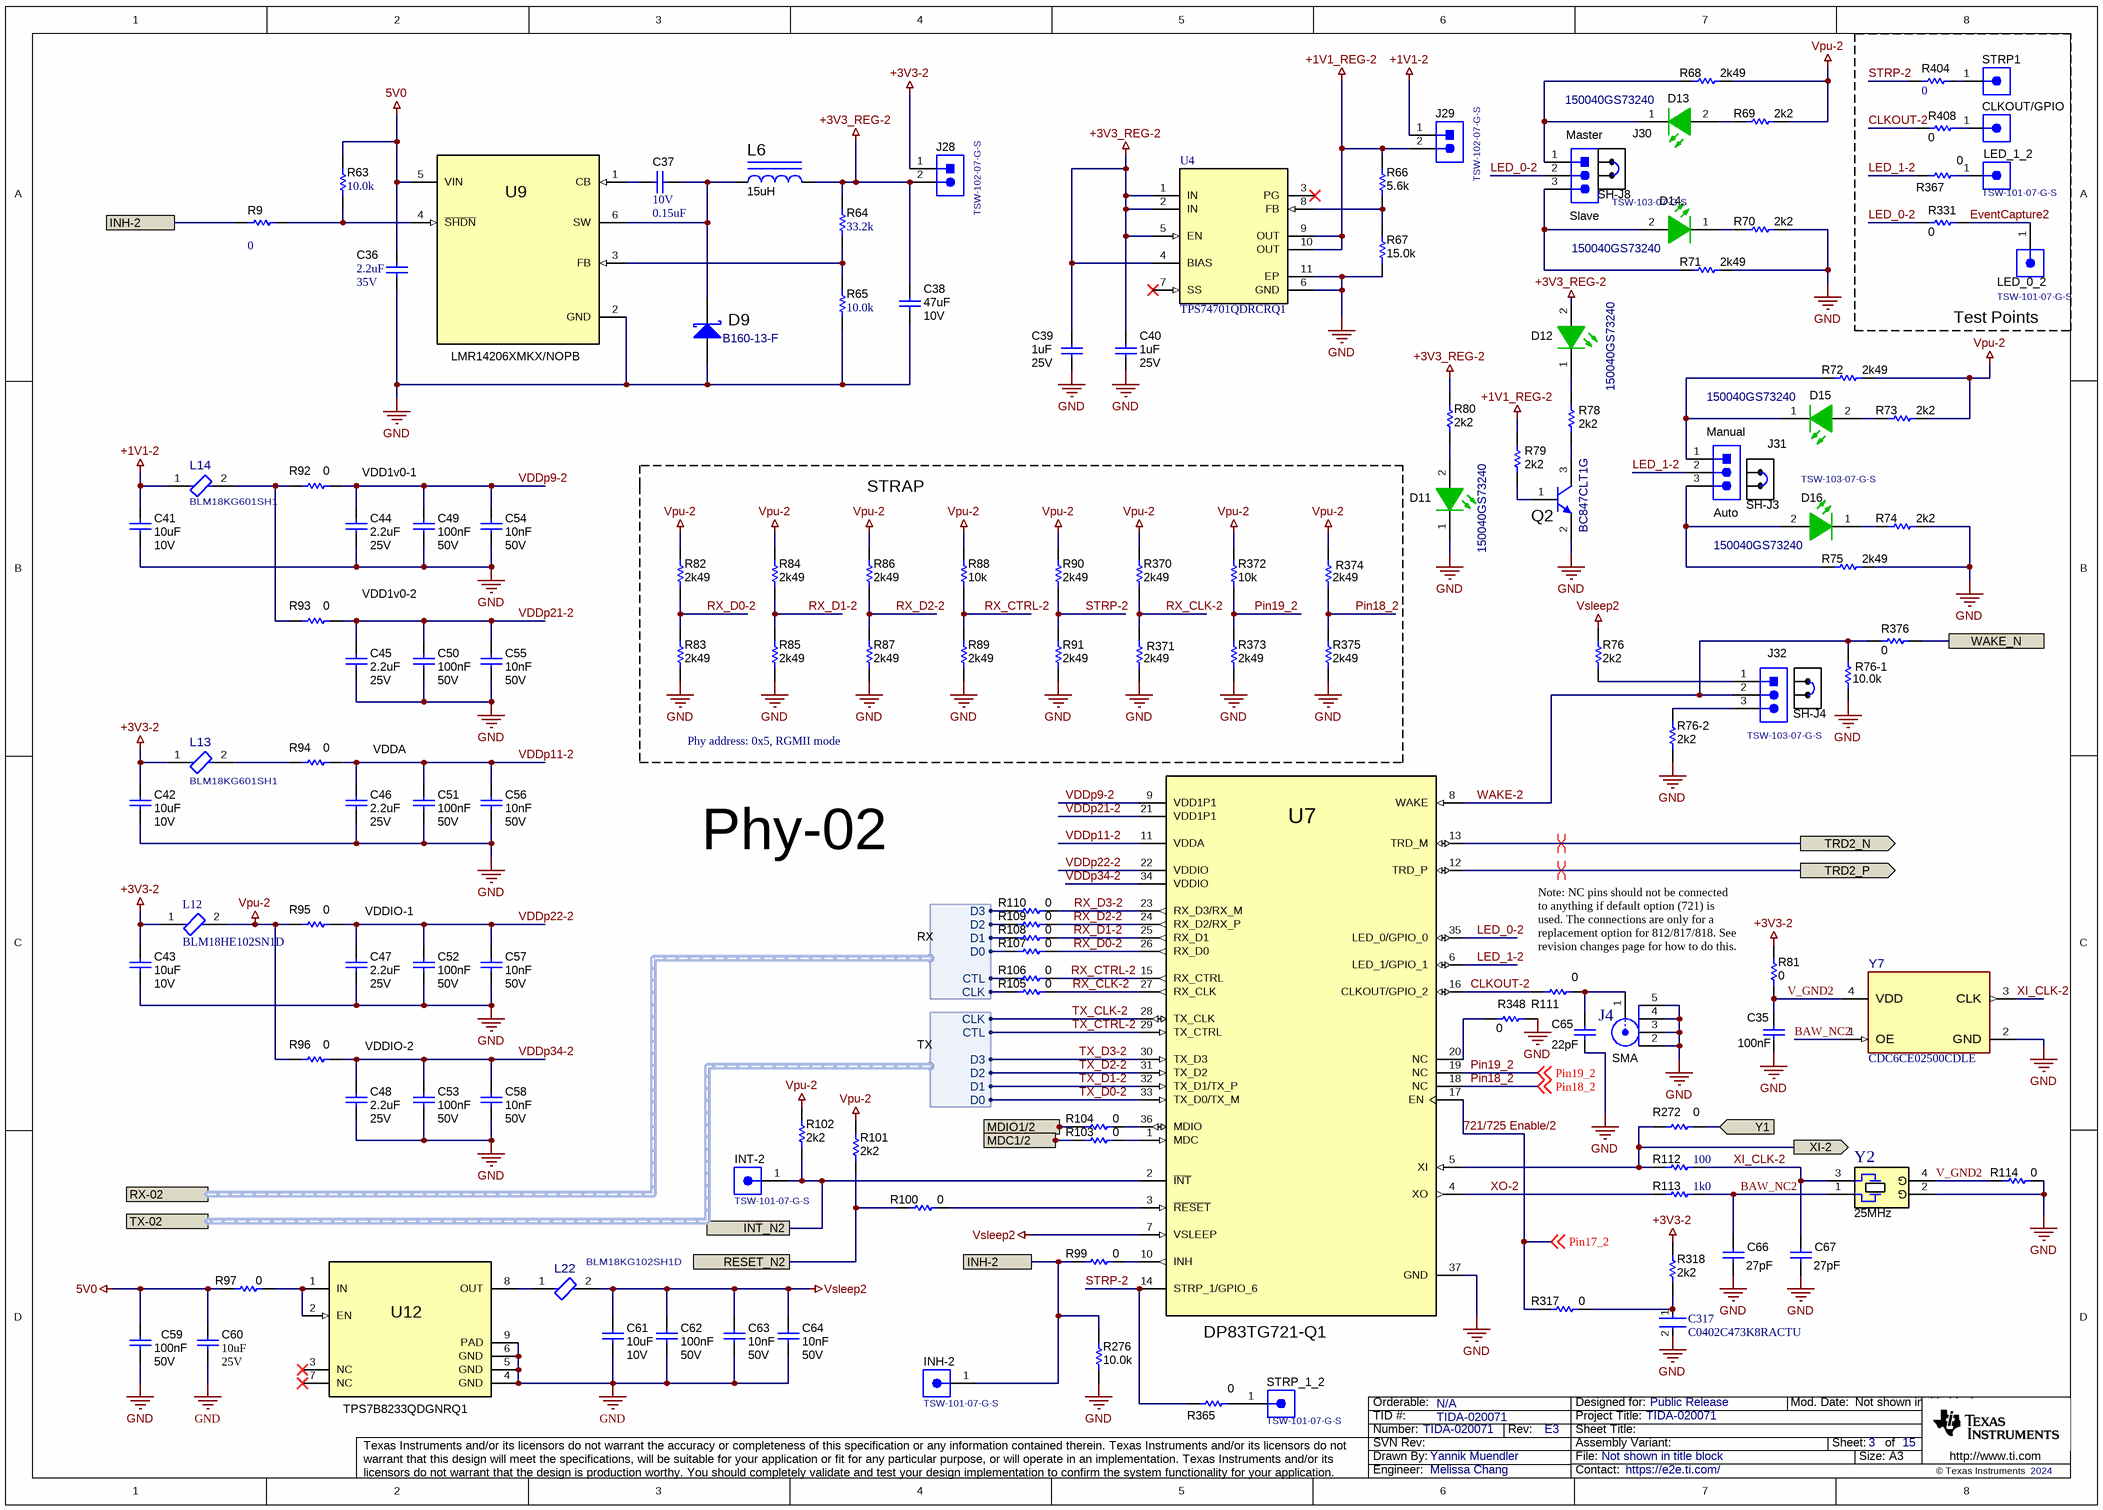
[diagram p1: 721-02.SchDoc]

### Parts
C35  ValueDisplayed: 100nF  [0402]  (hidden comment: C1005X5R1H104K050BB)
C36  VDC_V: 35V  ValueDisplayed: 2.2uF  [0603]  (hidden comment: C1608X5R1V225K080AC)
C37  VDC_V: 10V  ValueDisplayed: 0.15uF  [0402]  (hidden comment: GRM155R61A154KE19D)
C38  VDC_V: 10V  ValueDisplayed: 47uF  [0805_HV]  (hidden comment: C2012X5R1A476M125AC)
C39  VDC_V: 25V  ValueDisplayed: 1uF  [0402]  (hidden comment: GRM155R61E105KA12D)
C40  VDC_V: 25V  ValueDisplayed: 1uF  [0402]  (hidden comment: GRM155R61E105KA12D)
C41  VDC_V: 10V  ValueDisplayed: 10uF  [0402]  (hidden comment: GRM155R61A106ME11)
C42  VDC_V: 10V  ValueDisplayed: 10uF  [0402]  (hidden comment: GRM155R61A106ME11)
C43  VDC_V: 10V  ValueDisplayed: 10uF  [0402]  (hidden comment: GRM155R61A106ME11)
C44  VDC_V: 25V  ValueDisplayed: 2.2uF  [0402]  (hidden comment: C1005X5R1E225K050BC)
C45  VDC_V: 25V  ValueDisplayed: 2.2uF  [0402]  (hidden comment: C1005X5R1E225K050BC)
C46  VDC_V: 25V  ValueDisplayed: 2.2uF  [0402]  (hidden comment: C1005X5R1E225K050BC)
C47  VDC_V: 25V  ValueDisplayed: 2.2uF  [0402]  (hidden comment: C1005X5R1E225K050BC)
C48  VDC_V: 25V  ValueDisplayed: 2.2uF  [0402]  (hidden comment: C1005X5R1E225K050BC)
C49  VDC_V: 50V  ValueDisplayed: 100nF  [0402]  (hidden comment: C1005X5R1H104K050BB)
C50  VDC_V: 50V  ValueDisplayed: 100nF  [0402]  (hidden comment: C1005X5R1H104K050BB)
C51  VDC_V: 50V  ValueDisplayed: 100nF  [0402]  (hidden comment: C1005X5R1H104K050BB)
C52  VDC_V: 50V  ValueDisplayed: 100nF  [0402]  (hidden comment: C1005X5R1H104K050BB)
C53  VDC_V: 50V  ValueDisplayed: 100nF  [0402]  (hidden comment: C1005X5R1H104K050BB)
C54  VDC_V: 50V  ValueDisplayed: 10nF  [0402]  (hidden comment: C0402C103J5RACTU)
C55  VDC_V: 50V  ValueDisplayed: 10nF  [0402]  (hidden comment: C0402C103J5RACTU)
C56  VDC_V: 50V  ValueDisplayed: 10nF  [0402]  (hidden comment: C0402C103J5RACTU)
C57  VDC_V: 50V  ValueDisplayed: 10nF  [0402]  (hidden comment: C0402C103J5RACTU)
C58  VDC_V: 50V  ValueDisplayed: 10nF  [0402]  (hidden comment: C0402C103J5RACTU)
C59  VDC_V: 50V  ValueDisplayed: 100nF  [0402]  (hidden comment: C1005X5R1H104K050BB)
C60  VDC_V: 25V  ValueDisplayed: 10uF  [0603]  (hidden comment: C1608X5R1E106M080AC)
C61  VDC_V: 10V  ValueDisplayed: 10uF  [0402]  (hidden comment: GRM155R61A106ME11)
C62  VDC_V: 50V  ValueDisplayed: 100nF  [0402]  (hidden comment: C1005X5R1H104K050BB)
C63  VDC_V: 50V  ValueDisplayed: 10nF  [0402]  (hidden comment: C0402C103J5RACTU)
C64  VDC_V: 50V  ValueDisplayed: 10nF  [0402]  (hidden comment: C0402C103J5RACTU)
C65  ValueDisplayed: 22pF  [0402]  (hidden comment: GRM1555C1H220FA01D)
C66  ValueDisplayed: 27pF  [0402]  (hidden comment: C0402C270J5GACTU)
C67  ValueDisplayed: 27pF  [0402]  (hidden comment: C0402C270J5GACTU)
C317  C0402C473K8RACTU  [FP-C0402-BB-MFG]
CLKOUT/GPIO  TSW-101-07-G-S  [TSW-101-07-G-S]  (value not drawn)
D9  B160-13-F  [SMA]
D11  150040GS73240  [WL-SMCC_0402_Green]
D12  150040GS73240  [WL-SMCC_0402_Green]
D13  150040GS73240  [WL-SMCC_0402_Green]
D14  150040GS73240  [WL-SMCC_0402_Green]
D15  150040GS73240  [WL-SMCC_0402_Green]
D16  150040GS73240  [WL-SMCC_0402_Green]
INH-2  TSW-101-07-G-S  [TSW-101-07-G-S]
INT-2  TSW-101-07-G-S  [TSW-101-07-G-S]
J4  CompType: SMA  [AMPHENOL_901-144-8RFX]  (hidden comment: 901-144-8RFX)
J28  TSW-102-07-G-S  [TSW-102-07-G-S]
J29  TSW-102-07-G-S  [TSW-102-07-G-S]
J30  TSW-103-07-G-S  [TSW-103-07-G-S]
J31  TSW-103-07-G-S  [TSW-103-07-G-S]
J32  TSW-103-07-G-S  [TSW-103-07-G-S]
L6  ValueDisplayed: 15uH  [WE-TPC-LH]  (hidden comment: 744053150)
L12  BLM18HE102SN1D  [FP-BLM18-0_15-t0_8-MFG]
L13  BLM18KG601SH1  [FP-BLM18KG601SH1_0603 (1608 Metric)-MFG]
L14  BLM18KG601SH1  [FP-BLM18KG601SH1_0603 (1608 Metric)-MFG]
L22  BLM18KG102SH1D  [FP-BLM18KG102SH1D_0603-MFG]
LED_0_2  TSW-101-07-G-S  [TSW-101-07-G-S]
LED_1_2  TSW-101-07-G-S  [TSW-101-07-G-S]
Q2  BC847CLT1G  [SOT-23]
R9  ValueDisplayed: 0  [0402]  (hidden comment: CRCW04020000Z0ED)
R63  ValueDisplayed: 10.0k  [0402]  (hidden comment: CRCW040210K0FKED)
R64  ValueDisplayed: 33.2k  [0402]  (hidden comment: CRCW040233K2FKED)
R65  ValueDisplayed: 10.0k  [0402]  (hidden comment: CRCW040210K0FKED)
R66  ValueDisplayed: 5.6k  [0402]  (hidden comment: CRCW04025K60JNED)
R67  ValueDisplayed: 15.0k  [0402]  (hidden comment: CRCW040215K0FKED)
R68  ValueDisplayed: 2k49  [0402]  (hidden comment: CRCW04022K49FKED)
R69  ValueDisplayed: 2k2  [0402]  (hidden comment: CRCW04022K20JNED)
R70  ValueDisplayed: 2k2  [0402]  (hidden comment: CRCW04022K20JNED)
R71  ValueDisplayed: 2k49  [0402]  (hidden comment: CRCW04022K49FKED)
R72  ValueDisplayed: 2k49  [0402]  (hidden comment: CRCW04022K49FKED)
R73  ValueDisplayed: 2k2  [0402]  (hidden comment: CRCW04022K20JNED)
R74  ValueDisplayed: 2k2  [0402]  (hidden comment: CRCW04022K20JNED)
R75  ValueDisplayed: 2k49  [0402]  (hidden comment: CRCW04022K49FKED)
R76  ValueDisplayed: 2k2  [0402]  (hidden comment: CRCW04022K20JNED)
R76-1  ValueDisplayed: 10.0k  [0402]  (hidden comment: CRCW040210K0FKED)
R76-2  ValueDisplayed: 2k2  [0402]  (hidden comment: CRCW04022K20JNED)
R78  ValueDisplayed: 2k2  [0402]  (hidden comment: CRCW04022K20JNED)
R79  ValueDisplayed: 2k2  [0402]  (hidden comment: CRCW04022K20JNED)
R80  ValueDisplayed: 2k2  [0402]  (hidden comment: CRCW04022K20JNED)
R81  ValueDisplayed: 0  [0402]  (hidden comment: ERJ-2GE0R00X)
R82  ValueDisplayed: 2k49  [0402]  (hidden comment: CRCW04022K49FKED)
R83  ValueDisplayed: 2k49  [0402]  (hidden comment: CRCW04022K49FKED)
R84  ValueDisplayed: 2k49  [0402]  (hidden comment: CRCW04022K49FKED)
R85  ValueDisplayed: 2k49  [0402]  (hidden comment: CRCW04022K49FKED)
R86  ValueDisplayed: 2k49  [0402]  (hidden comment: CRCW04022K49FKED)
R87  ValueDisplayed: 2k49  [0402]  (hidden comment: CRCW04022K49FKED)
R88  ValueDisplayed: 10k  [0402]  (hidden comment: RC0402FR-0710KL)
R89  ValueDisplayed: 2k49  [0402]  (hidden comment: CRCW04022K49FKED)
R90  ValueDisplayed: 2k49  [0402]  (hidden comment: CRCW04022K49FKED)
R91  ValueDisplayed: 2k49  [0402]  (hidden comment: CRCW04022K49FKED)
R92  ValueDisplayed: 0  [0402]  (hidden comment: CRCW04020000Z0EDHP)
R93  ValueDisplayed: 0  [0402]  (hidden comment: CRCW04020000Z0EDHP)
R94  ValueDisplayed: 0  [0402]  (hidden comment: CRCW04020000Z0EDHP)
R95  ValueDisplayed: 0  [0402]  (hidden comment: CRCW04020000Z0EDHP)
R96  ValueDisplayed: 0  [0402]  (hidden comment: CRCW04020000Z0EDHP)
R97  ValueDisplayed: 0  [0402]  (hidden comment: CRCW04020000Z0EDHP)
R99  ValueDisplayed: 0  [0402]  (hidden comment: CRCW04020000Z0EDHP)
R100  ValueDisplayed: 0  [0402]  (hidden comment: CRCW04020000Z0EDHP)
R101  ValueDisplayed: 2k2  [0402]  (hidden comment: CRCW04022K20JNED)
R102  ValueDisplayed: 2k2  [0402]  (hidden comment: CRCW04022K20JNED)
R103  ValueDisplayed: 0  [0402]  (hidden comment: CRCW04020000Z0EDHP)
R104  ValueDisplayed: 0  [0402]  (hidden comment: CRCW04020000Z0EDHP)
R105  ValueDisplayed: 0  [0402]  (hidden comment: CRCW04020000Z0EDHP)
R106  ValueDisplayed: 0  [0402]  (hidden comment: CRCW04020000Z0EDHP)
R107  ValueDisplayed: 0  [0402]  (hidden comment: CRCW04020000Z0EDHP)
R108  ValueDisplayed: 0  [0402]  (hidden comment: CRCW04020000Z0EDHP)
R109  ValueDisplayed: 0  [0402]  (hidden comment: CRCW04020000Z0EDHP)
R110  ValueDisplayed: 0  [0402]  (hidden comment: CRCW04020000Z0EDHP)
R111  ValueDisplayed: 0  [0402]  (hidden comment: ERJ-2GE0R00X)
R112  ValueDisplayed: 100  [0402]  (hidden comment: CRCW0402100RFKED)
R113  ValueDisplayed: 1k0  [0402]  (hidden comment: CRCW04021K00FKED)
R114  ValueDisplayed: 0  [0402]  (hidden comment: ERJ-2GE0R00X)
R272  ValueDisplayed: 0  [0402]  (hidden comment: ERJ-2GE0R00X)
R276  ValueDisplayed: 10.0k  [0402]  (hidden comment: CRCW040210K0FKED)
R317  ValueDisplayed: 0  [0402]  (hidden comment: CRCW04020000Z0EDHP)
R318  ValueDisplayed: 2k2  [0402]  (hidden comment: CRCW04022K20JNED)
R331  ValueDisplayed: 0  [0402]  (hidden comment: ERJ-2GE0R00X)
R348  ValueDisplayed: 0  [0402]  (hidden comment: ERJ-2GE0R00X)
R365  ValueDisplayed: 0  [0402]  (hidden comment: ERJ-2GE0R00X)
R367  ValueDisplayed: 0  [0402]  (hidden comment: ERJ-2GE0R00X)
R370  ValueDisplayed: 2k49  [0402]  (hidden comment: CRCW04022K49FKED)
R371  ValueDisplayed: 2k49  [0402]  (hidden comment: CRCW04022K49FKED)
R372  ValueDisplayed: 10k  [0402]  (hidden comment: RC0402FR-0710KL)
R373  ValueDisplayed: 2k49  [0402]  (hidden comment: CRCW04022K49FKED)
R374  ValueDisplayed: 2k49  [0402]  (hidden comment: CRCW04022K49FKED)
R375  ValueDisplayed: 2k49  [0402]  (hidden comment: CRCW04022K49FKED)
R376  ValueDisplayed: 0  [0402]  (hidden comment: ERJ-2GE0R00X)
R404  ValueDisplayed: 0  [0402]  (hidden comment: ERJ-2GE0R00X)
R408  ValueDisplayed: 0  [0402]  (hidden comment: ERJ-2GE0R00X)
SH-J3  881545-2  [TE_881545-2]  (value not drawn)  (mechanical)
SH-J4  881545-2  [TE_881545-2]  (value not drawn)  (mechanical)
SH-J8  881545-2  [TE_881545-2]  (value not drawn)  (mechanical)
STRP1  TSW-101-07-G-S  [TSW-101-07-G-S]  (value not drawn)
STRP_1_2  TSW-101-07-G-S  [TSW-101-07-G-S]
U4  TPS74701QDRCRQ1  [DRC0010A]
U7  PartNumber: DP83TG721-Q1  [RND0036A]  (hidden comment: DP83TG720SWRNDRQ1)
U9  LMR14206XMKX/NOPB  [DDC0006A_N]
U12  TPS7B8233QDGNRQ1  [DGN0008D_N]
Y2  Frequency_Fixed: 25MHz  [Abracon_ABM8AIG]  (hidden comment: ABM8AIG-25.000MHZ-12-2Z-T3)
Y7  CDC6CE02500CDLE  [DLE0004A-MFG]

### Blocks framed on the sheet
Test Points: CLKOUT/GPIO LED_0_2 LED_1_2 R331 R367 R404 R408 STRP1
STRAP: R82-R91 R370-R375

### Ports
INH-2, INT_N2, MDC1/2, MDIO1/2, RESET_N2, RX-02 (harness RX), TRD2_N (out), TRD2_P (out), TX-02 (harness TX), WAKE_N, XI-2 (out), Y1 (in)

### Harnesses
TX: D0, D1, D2, D3, CTL, CLK
RX: D0, D1, D2, D3, CTL, CLK

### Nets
5V0: C36.1 C59.1 C60.1 R63.2 R97.2 U9.5(VIN)
+1V1-2: C41.1 J29.1 L14.1
+1V1_REG-2: J29.2 R66.2 R79.2 U4.9(OUT) U4.10(OUT)
+3V3-2: C42.1 C43.1 J28.1 L12.1 L13.1 R81.1 R318.1
+3V3_REG-2: C38.1 C39.1 C40.1 D12.2(A) J28.2 L6.2 R64.2 R80.2 U4.1(IN) U4.2(IN) U4.4(BIAS) U4.5(EN)
GND: C35.2 C36.2 C38.2 C39.2 C40.2 C41.2 C42.2 C43.2 C44.2 C45.2 C46.2 C47.2 C48.2 C49.2 C50.2 C51.2 C52.2 C53.2 C54.2 C55.2 C56.2 C57.2 C58.2 C59.2 C60.2 C61.2 C62.2 C63.2 C64.2 C65.2 C66.2 C67.2 C317.2 D9.2(A) D11.1(K) J4.2 J4.3 J4.4 J4.5 Q2.2(E) R65.1 R67.1 R70.2 R71.2 R74.2 R75.2 R76-1.1 R76-2.2 R83.1 R85.1 R87.1 R89.1 R91.1 R114.2 R276.1 R348.2 R371.1 R373.1 R375.1 U4.6(GND) U4.11(EP) U7.37(GND) U9.2(GND) U12.4(GND) U12.5(GND) U12.6(GND) U12.9(PAD) Y2.2(GND) Y7.2(GND)
Vpu-2: L12.2 R68.2 R69.2 R72.2 R73.2 R82.2 R84.2 R86.2 R88.2 R90.2 R95.2 R96.2 R101.2 R102.2 R370.2 R372.2 R374.2
Vsleep2: C61.1 C62.1 C63.1 C64.1 L22.2 R76.1 U7.7(VSLEEP)
721/725 Enable/2: R317.2 U7.17(EN) ; off-sheet Pin17_2  [also labelled Pin17_2]
BAW_NC2: C66.1 R113.1 Y2.1 Y7.1(OE)
CLKOUT-2: R111.1 R408.1 U7.16(CLKOUT/GPIO_2)
EventCapture2: LED_0_2.1 R331.2
INH-2: INH-2.1 R9.1 R99.2 R276.2 ; port INH-2
INT_N2: INT-2.1 R102.1 U7.2(~{INT}) ; port INT_N2
LED_0-2: J30.2 R331.1 U7.35(LED_0/GPIO_0)
LED_1-2: J31.2 R367.1 U7.6(LED_1/GPIO_1)
MDC1/2: R103.2 ; port MDC1/2
MDIO1/2: R104.2 ; port MDIO1/2
P1-R2-RCLK: R105.2 ; port RX-02.CLK
P1-R2-RCTL: R106.2 ; port RX-02.CTL
P1-R2-RD0: R107.2 ; port RX-02.D0
P1-R2-RD1: R108.2 ; port RX-02.D1
P1-R2-RD2: R109.2 ; port RX-02.D2
P1-R2-RD3: R110.2 ; port RX-02.D3
Pin18_2: R374.1 R375.2 U7.18(NC) ; off-sheet Pin18_2
Pin19_2: R372.1 R373.2 U7.19(NC) ; off-sheet Pin19_2
RESET_N2: R100.2 R101.1 ; port RESET_N2
RX_CLK-2: R105.1 R370.1 R371.2 U7.27(RX_CLK)
RX_CTRL-2: R88.1 R89.2 R106.1 U7.15(RX_CTRL)
RX_D0-2: R82.1 R83.2 R107.1 U7.26(RX_D0)
RX_D1-2: R84.1 R85.2 R108.1 U7.25(RX_D1)
RX_D2-2: R86.1 R87.2 R109.1 U7.24(RX_D2/RX_P)
RX_D3-2: R110.1 U7.23(RX_D3/RX_M)
STRP-2: R90.1 R91.2 R365.1 R404.1 U7.14(STRP_1/GPIO_6)
TRD2_N: U7.13(TRD_M) ; port TRD2_N
TRD2_P: U7.12(TRD_P) ; port TRD2_P
TX_CLK-2: U7.28(TX_CLK) ; port TX-02.CLK
TX_CTRL-2: U7.29(TX_CTRL) ; port TX-02.CTL
TX_D0-2: U7.33(TX_D0/TX_M) ; port TX-02.D0
TX_D1-2: U7.32(TX_D1/TX_P) ; port TX-02.D1
TX_D2-2: U7.31(TX_D2) ; port TX-02.D2
TX_D3-2: U7.30(TX_D3) ; port TX-02.D3
V_GND2: C35.1 R81.2 R114.1 Y2.4(GND) Y7.4(VDD)
VDDp9-2: C44.1 C49.1 C54.1 R92.1 U7.9(VDD1P1)
VDDp11-2: C46.1 C51.1 C56.1 R94.1 U7.11(VDDA)
VDDp21-2: C45.1 C50.1 C55.1 R93.1 U7.21(VDD1P1)
VDDp22-2: C47.1 C52.1 C57.1 R95.1 U7.22(VDDIO)
VDDp34-2: C48.1 C53.1 C58.1 R96.1 U7.34(VDDIO)
WAKE-2: J32.2 R76-1.2 R376.1 U7.8(WAKE)
WAKE_N: R376.2 ; port WAKE_N
XI-2: R112.2 R272.1 U7.5(XI) ; port XI-2
XI_CLK-2: C67.1 R112.1 Y2.3 Y7.3(CLK)
XO-2: R113.2 U7.4(XO)
Y1: R272.2 ; port Y1
NetC37_1: C37.1 D9.1(K) L6.1 U9.6(SW)
NetC37_2: C37.2 U9.1(CB)
NetC65_1: C65.1 J4.1 R111.2
NetC317_1: C317.1 R317.1 R318.2
NetCLKOUT/GPIO_1: CLKOUT/GPIO.1 R408.2
NetD11_2: D11.2(A) R80.1
NetD12_1: D12.1(K) R78.2
NetD13_1: D13.1(K) J30.1 R68.1
NetD13_2: D13.2(A) R69.1
NetD14_1: D14.1(K) R70.1
NetD14_2: D14.2(A) J30.3 R71.1
NetD15_1: D15.1(K) J31.1 R72.1
NetD15_2: D15.2(A) R73.1
NetD16_1: D16.1(K) R74.1
NetD16_2: D16.2(A) J31.3 R75.1
NetJ32_1: J32.1 R76.2
NetJ32_3: J32.3 R76-2.1
NetL13_2: L13.2 R94.2
NetL14_2: L14.2 R92.2 R93.2
NetL22_1: L22.1 U12.8(OUT)
NetLED_1_2_1: LED_1_2.1 R367.2
NetQ2_1: Q2.1(B) R79.1
NetQ2_3: Q2.3(C) R78.1
NetR9_2: R9.2 R63.1 U9.4(~{SHDN})
NetR64_1: R64.1 R65.2 U9.3(FB)
NetR66_1: R66.1 R67.2 U4.8(FB)
NetR97_1: R97.1 U12.1(IN) U12.2(EN)
NetR99_1: R99.1 U7.10(INH)
NetR100_1: R100.1 U7.3(~{RESET})
NetR103_1: R103.1 U7.1(MDC)
NetR104_1: R104.1 U7.36(MDIO)
NetR348_1: R348.1 U7.20(NC)
NetR365_2: R365.2 STRP_1_2.1
NetR404_2: R404.2 STRP1.1

Not connected (* = marked no-connect by the designer): U4 3(PG)* 7(SS)*; U12 3(NC)* 7(NC)*

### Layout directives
differential pair: TRD2_N, TRD2_P

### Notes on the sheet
- (near J30) Master
- (near J30) Slave
- (near J31) Manual
- VDD1v0-1
- Auto
- VDD1v0-2
- VDDA
- Phy address: 0x5, RGMII mode
- Phy-02
- VDDIO-1
- Note: NC pins should not be connected to anything if default option (721) is used. The connections are only for a replacement option for 812/817/818. See revision changes page for how to do this.
- VDDIO-2

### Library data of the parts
C35 = CMP-0006279-2: as C1 on sheet 721-01
C36 = CMP-0007020-5: as C2 on sheet 721-01
C37 = CMP-0006567-2: as C3 on sheet 721-01
C38 = CMP-0007825-2: as C4 on sheet 721-01
C39 C40 = CMP-0006608-2: as C5 on sheet 721-01
C41-C43 C61 = CMP-0006564-2: as C7 on sheet 721-01
C44-C48 = CMP-0006278-2: as C10 on sheet 721-01
C49-C53 C59 C62 = CMP-0006279-2: as C15 on sheet 721-01
C54-C58 C63 C64 = CMP-0006236-2: as C20 on sheet 721-01
C60 = CMP-0007007-5: as C26 on sheet 721-01
C65 = CMP-0006438-2: as C31 on sheet 721-01
C66 C67 = CMP-0750098-1: as C32 on sheet 721-01
C317 = CMP-2008-02147-2: as C314 on sheet 721-01
CLKOUT/GPIO INH-2 INT-2 LED_0_2 LED_1_2 STRP1 STRP_1_2 = CMP-0075403-1: as INH-1 on sheet 721-01
D9 = CMP-0028389-2: as D1 on sheet 721-01
D11-D16 = CMP-0081765-2: as D2 on sheet 721-01
J4 = CMP-0055833-1: as J3 on sheet 721-01
J28 J29 = CMP-0075405-3: as J13 on sheet 721-01
J30-J32 = CMP-0075407-2: as J15 on sheet 721-01
L6 = CMP-0064420-2: as L5 on sheet 721-01
L12 = CMP-0686-00363-3: as L9 on sheet 721-01
L13 L14 = CMP-0089848-1: as L10 on sheet 721-01
L22 = CMP-0089381-1: as L21 on sheet 721-01
Q2 = CMP-0000376-2: as Q1 on sheet 721-01
R9 = CMP-0026822-1: as R3 on sheet 721-01
R63 R65 = CMP-0025958-3: as R10 on sheet 721-01
R64 = CMP-0026298-2: as R11 on sheet 721-01
R66 = CMP-0026952-5: as R13 on sheet 721-01
R67 = CMP-0026027-3: as R14 on sheet 721-01
R68 R71 R72 R75 R82-R87 R89-R91 R370 R371 R373-R375 = CMP-0026237-2: as R15 on sheet 721-01
R69 R70 R73 R74 R76 R76-2 R78-R80 R101 R102 R318 = CMP-0026890-5: as R16 on sheet 721-01
R76-1 R276 = CMP-0025958-1: as R23-1 on sheet 721-01
R81 R111 R114 R272 R331 R348 R365 R367 R376 R408 = CMP-0026992-3: as R24 on sheet 721-01
R88 R372 = CMP-0078669-1: RES, 10.0 k, 1%, 0.063 W, 0402; Manufacturer: Yageo America; Power_W: 63mW; Green_Lifecycle: Active; TempCo: 100 ppm/C; Value_Code: 10k0; Green_REACh: Passed; Value: 10.0k; EIA_Code: E96; SizeX_mm: 1; SizeY_mm: 0.5; SizeZ_mm: 0.6; Value2: 0.063W; AEC Qualified: N; AEC Category: Q200
R92-R97 R99 R100 R103-R110 R317 = CMP-0081856-1: as R39 on sheet 721-01
R112 = CMP-0025951-3: as R59 on sheet 721-01
R113 = CMP-0026071-3: as R60 on sheet 721-01
R404 = CMP-0026992-3: RES, 0, 5%, 0.1 W, AEC-Q200 Grade 0, 0402; Manufacturer: Panasonic; Power_W: 100mW; TempCo: 600 ppm/C; Value_Code: 0000; Value: 0; EIA_Code: E24; SizeX_mm: 1; SizeY_mm: 0.5; SizeZ_mm: 0.6; Value2: 0.1W; AEC Qualified: Y; VDC_V: 50V; AEC Category: Q200; SizeAreaWB_mm2: 3
SH-J3 SH-J4 SH-J8 = 881545-2: as SH-J1 on sheet 721-01
U4 = CMP-0036364-1: as U2 on sheet 721-01
U7 = CMP-0085268-1: as U1 on sheet 721-01
U9 = CMP-0076377-2: as U3 on sheet 721-01
U12 = CMP-0013312-4: as U6 on sheet 721-01
Y2 = CMP-0004682-5: as Y1 on sheet 721-01
Y7 = CMP-0001498-1: as Y6 on sheet 721-01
